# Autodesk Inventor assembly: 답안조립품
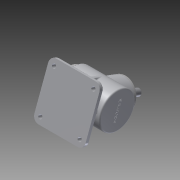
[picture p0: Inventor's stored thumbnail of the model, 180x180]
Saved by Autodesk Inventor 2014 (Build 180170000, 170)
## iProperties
Created: 2015-07
Part Number: 답안조립품
Document SubType Name: Assembly
Designer: user
Author: user
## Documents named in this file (14)
- C:\Users\user\Desktop\450706V1015\답안조립품.iam
- C:\Users\user\Desktop\450706V1015\1-본체.ipt
- C:\Users\user\Desktop\450706V1015\메인 축.ipt
- 메인 축.ipt
- C:\Users\user\Desktop\450706V1015\서브 축.ipt
- 서브 축.ipt
- C:\Users\user\Desktop\450706V1015\커버.ipt
- C:\Users\user\Desktop\450706V1015\베어링 6203.ipt
- C:\Users\user\Desktop\450706V1015\오일실.ipt
- C:\Users\user\Desktop\450706V1015\메인 베벨기어.ipt
- C:\Users\user\Desktop\450706V1015\키 5x5.ipt
- C:\Users\user\Desktop\450706V1015\서브 베벨기어.ipt
- C:\Users\user\Desktop\450706V1015\키 4x4.ipt
- C:\Users\user\Desktop\450706V1015\M4.ipt
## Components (9 placed, 2 different names)
1. 1-본체:1 — Mate:1, Mate:2, Insert:3, Mate:3, Mate:4, Insert:9
2. M4:2 — Insert:13
3. M4:3
4. M4:4
5. M4:5
6. M4:1 — Insert:12
7. M4:6
8. M4:7
9. M4:8
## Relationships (8: Mate 4, Insert 4)
- Mate:1: 1-본체:1
- Mate:2: 1-본체:1
- Insert:3: 1-본체:1
- Mate:3: 1-본체:1
- Mate:4: 1-본체:1
- Insert:9: 1-본체:1
- Insert:12: M4:1
- Insert:13: M4:2
